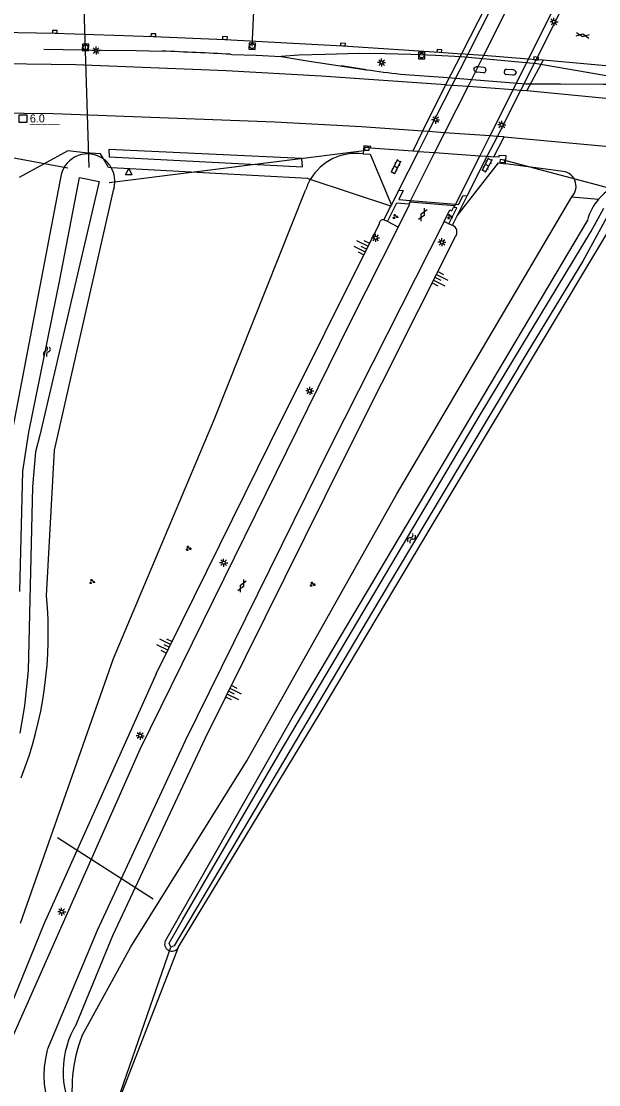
# Model space of a CAD drawing. Extents: x 133000 to 136000, y 400500 to 403500.
# Drawn here: x 134131.9 to 134221.9, y 401012.6 to 401178.4 of the extents above; entities that cross this region are included whole.
import ezdxf

# ---------------------------------------------------------------- set-up
doc = ezdxf.new("R2010")
doc.units = 0
for name, color, linetype in [('gg-afsc-faunaraster', 7, 'Continuous'), ('gg-afsc-hekwerk', 7, 'Continuous'), ('gg-bbg-pilaar viaduct of brug', 7, 'Continuous'), ('gg-knt-BGT kruinlijn', 7, 'Continuous'), ('gg-knt-bovenkant onderkant talud', 7, 'Continuous'), ('gg-knt-verharding', 7, 'Continuous'), ('gg-knt-verharding nz', 7, 'Continuous'), ('gg-kntw-bovenkant insteek waterloop', 7, 'Continuous'), ('gg-kntw-greppel-droge sloot', 7, 'Continuous'), ('gg-kntw-waterlijn', 7, 'Continuous'), ('gg-kwrk-duiker nz buis', 7, 'Continuous'), ('gg-kwrk-kunstwerk', 7, 'Continuous'), ('gg-kwrk-kunstwerk niveau 01', 7, 'Continuous'), ('gt-anno-nummer hm paal', 7, 'Continuous'), ('gt-grn-groengrens', 7, 'Continuous'), ('gt-grn-weggrens', 7, 'Continuous'), ('gt-knt-geleideconstructie', 7, 'Continuous'), ('gt-symb-gesloten verharding', 7, 'Continuous'), ('gt-symb-groenvak', 7, 'Continuous'), ('gt-symb-hm paal', 7, 'Continuous'), ('gt-symb-klinker verharding', 7, 'Continuous'), ('gt-symb-kolk', 7, 'Continuous'), ('gt-symb-lichtmast', 7, 'Continuous'), ('gt-symb-rioolschacht', 7, 'Continuous'), ('gt-symb-talud symbool', 7, 'Continuous'), ('gt-symb-waterafsluiter', 7, 'Continuous'), ('gt-symb-watersymbool', 7, 'Continuous')]:
    doc.layers.add(name, color=color, linetype=linetype)

# ---------------------------------------------------------------- blocks, each defined once
blk = doc.blocks.new('gt0-KOLK')
at = {"layer": 'gt-symb-kolk'}
blk.add_lwpolyline([(0, 0), (0.38, 0), (0.38, 0.4), (-0.37, 0.4), (-0.37, 0), (0, 0)], dxfattribs=at)
blk = doc.blocks.new('gt0-LMAST')
at = {"layer": 'gt-symb-lichtmast'}
for p, q in [((-0.18, 0.17), (-0.45, 0.44)), ((-0.01, 0.25), (-0.01, 0.62)), ((0.17, 0.17), (0.44, 0.44)), ((-0.26, 0), (-0.63, 0)), ((-0.18, -0.18), (-0.45, -0.45)), ((-0.01, -0.25), (-0.01, -0.63)), ((0.44, -0.45), (0.17, -0.18)), ((0.24, 0), (0.62, 0))]:
    blk.add_line(p, q, dxfattribs=at)
blk.add_circle((-0.01, 0), 0.25, dxfattribs=at)
blk = doc.blocks.new('gt0-GESVH1')
at = {"layer": 'gt-symb-gesloten verharding'}
for p, q in [((-0.99, -0.26), (0.01, 0.24)), ((0.01, -0.26), (-0.99, 0.24)), ((0.01, 0.24), (1.01, -0.26)), ((1.01, 0.24), (0.01, -0.26))]:
    blk.add_line(p, q, dxfattribs=at)
blk = doc.blocks.new('gt0-KL1')
at = {"layer": 'gt-symb-klinker verharding'}
for p, q in [((-1.15, 0.3), (1.15, 0.3)), ((-1, -0.3), (-1, 0.3)), ((-0.5, 0.3), (-0.5, 0.45)), ((0, -0.3), (0, 0.3)), ((0.5, 0.3), (0.5, 0.45)), ((1, -0.3), (1, 0.3)), ((-1.15, -0.3), (1.15, -0.3)), ((-0.5, -0.45), (-0.5, -0.3)), ((0.5, -0.45), (0.5, -0.3))]:
    blk.add_line(p, q, dxfattribs=at)
blk = doc.blocks.new('gt0-RS')
at = {"layer": 'gt-symb-rioolschacht'}
blk.add_lwpolyline([(-0.5, -0.5), (0.5, -0.5), (0.5, 0.5), (-0.5, 0.5)], close=True, dxfattribs=at)
blk.add_circle((0, 0), 0.375, dxfattribs=at)
blk = doc.blocks.new('gt0-WA')
at = {"layer": 'gt-symb-watersymbool'}
for centre, start, end in [((-0.32, 0.02), 28.0725, 151.9275), ((0.43, 0.42), 208.0725, 331.9275), ((-0.32, -0.43), 28.0725, 151.9275), ((0.43, -0.03), 208.0725, 331.9275)]:
    blk.add_arc(centre, 0.425, start, end, dxfattribs=at)
blk = doc.blocks.new('gt0-TALUD_1')
at = {"layer": 'gt-symb-talud symbool'}
for p, q in [((-1, -1), (-1, 0)), ((0.5, -2), (0.5, 0)), ((-0.5, -2), (-0.5, 0)), ((0, -1), (0, 0)), ((1, -1), (1, 0))]:
    blk.add_line(p, q, dxfattribs=at)
blk = doc.blocks.new('gt0-GRVAK')
at = {"layer": 'gt-symb-groenvak'}
for p, q in [((-0.11, 0.19), (-0.23, 0.24)), ((-0.18, 0.15), (0.09, 0.15)), ((-0.09, 0.21), (-0.16, 0.32)), ((-0.05, 0.21), (-0.05, 0.39)), ((0, 0.21), (0.06, 0.32)), ((0.01, 0.19), (0.13, 0.24)), ((0.26, -0.05), (0.2, 0.06)), ((0.3, -0.05), (0.3, 0.13)), ((0.35, -0.05), (0.41, 0.06)), ((-0.25, -0.23), (-0.36, -0.18)), ((-0.32, -0.26), (-0.05, -0.26)), ((-0.23, -0.21), (-0.29, -0.1)), ((-0.18, -0.2), (-0.18, -0.02)), ((-0.14, -0.21), (-0.07, -0.1)), ((-0.12, -0.23), (0, -0.18)), ((0.24, -0.07), (0.12, -0.02)), ((0.17, -0.11), (0.44, -0.11)), ((0.37, -0.07), (0.49, -0.02))]:
    blk.add_line(p, q, dxfattribs=at)
blk = doc.blocks.new('gt0-WAFSL')
at = {"layer": 'gt-symb-waterafsluiter'}
for p, q in [((-0.5, -0.33), (0, 0.67)), ((0, 0.67), (0.5, -0.33)), ((0.5, -0.33), (-0.5, -0.33))]:
    blk.add_line(p, q, dxfattribs=at)
blk = doc.blocks.new('gt0-HMpaal')
at = {"layer": 'gt-symb-hm paal'}
blk.add_lwpolyline([(-0.6, 0.6), (0.6, 0.6), (0.6, -0.6), (-0.6, -0.6)], close=True, dxfattribs=at)

msp = doc.modelspace()

# ---------------------------------------------------------------- linework, layer by layer
at = {"layer": 'gg-afsc-faunaraster'}
msp.add_lwpolyline([(134144.24, 401157.74), (134141.86, 401157.94), (134139.16, 401158.24), (134131.54, 401154.05)], dxfattribs=at)
at = {"layer": 'gg-afsc-hekwerk'}
for p, q in [((134144.71, 401156.96), (134144.24, 401157.74)), ((134189.51, 401149.59), (134176.97, 401153.77))]:
    msp.add_line(p, q, dxfattribs=at)
for points in [[(134145.94, 401155.6), (134145.52, 401155.62), (134144.71, 401156.96)], [(134176.97, 401153.77), (134176.52, 401153.92), (134145.94, 401155.6)]]:
    msp.add_lwpolyline(points, dxfattribs=at)
at = {"layer": 'gg-bbg-pilaar viaduct of brug'}
for p, q in [((134203.09, 401171.33), (134203.06, 401171.33)), ((134204.05, 401171.22), (134203.09, 401171.33)), ((134204.35, 401170.88), (134204.34, 401170.72)), ((134207.24, 401170.75), (134207.21, 401170.49)), ((134207.55, 401170.98), (134208.46, 401170.9)), ((134203.98, 401170.41), (134202.96, 401170.51)), ((134208.55, 401170.05), (134207.48, 401170.15))]:
    msp.add_line(p, q, dxfattribs=at)
for centre, radius, start, end in [((134203, 401170.69), 0.644, 84.3695, 154.1173), ((134203.04, 401171.15), 0.644, 195.6872, 240.3909), ((134203.04, 401171.16), 0.658, 240.5941, 263.1005), ((134204, 401170.75), 0.337, 265.9363, 355.1614), ((134204.01, 401170.88), 0.338, 359.975, 82.1786), ((134207.55, 401170.66), 0.32, 89.8543, 164.6529), ((134208.45, 401170.19), 0.706, 20.0302, 88.7607), ((134207.53, 401170.47), 0.323, 174.8818, 260.4784), ((134208.6, 401170.59), 0.535, 264.2303, 343.4292)]:
    msp.add_arc(centre, radius, start, end, dxfattribs=at)
at = {"layer": 'gg-knt-BGT kruinlijn'}
for p, q in [((134182.39, 401110.61), (134199.61, 401144.85)), ((134160.63, 401066.66), (134182.39, 401110.61)), ((134152.95, 401076.65), (134135.39, 401037.62)), ((134146.19, 401035.83), (134160.63, 401066.66)), ((134135.39, 401037.62), (134126.26, 401015.13)), ((134140.5, 401022.08), (134146.19, 401035.83))]:
    msp.add_line(p, q, dxfattribs=at)
msp.add_lwpolyline([(134152.95, 401076.65), (134170.76, 401112.81), (134187.71, 401146.81)], dxfattribs=at)
for centre, radius, start, end in [((134188.31, 401146.88), 0.607, 77.8115, 186.4309), ((134198.68, 401145.55), 1.16, 323.3097, 67.6114), ((134152.73, 401014.63), 14.32, 148.6447, 209.1066)]:
    msp.add_arc(centre, radius, start, end, dxfattribs=at)
at = {"layer": 'gg-knt-bovenkant onderkant talud'}
for p, q in [((134216.02, 401155.04), (134207.41, 401156.18)), ((134161.92, 401116.17), (134176.23, 401152.1))]:
    msp.add_line(p, q, dxfattribs=at)
msp.add_lwpolyline([(134141.35, 401020.16), (134148.99, 401034.06), (134167.08, 401063.08), (134190.43, 401104.61), (134217.74, 401151.06)], dxfattribs=at)
for centre, radius, start, end in [((134184.04, 401149.64), 8.19, 81.9014, 149.7715), ((134216.08, 401152.71), 2.33, 315.1357, 91.47), ((134184.01, 401149.65), 8.16, 149.7381, 162.5226), ((134162.24, 401011.96), 22.44, 158.5636, 191.0401)]:
    msp.add_arc(centre, radius, start, end, dxfattribs=at)
at = {"layer": 'gg-knt-verharding'}
for p, q in [((134200.52, 401173.35), (134198.06, 401168.55)), ((134213.26, 401172.35), (134210.75, 401167.66)), ((134213.26, 401172.35), (134212.2, 401172.44)), ((134209.81, 401167.72), (134210.75, 401167.66)), ((134194.47, 401161.3), (134192.95, 401158.2)), ((134205.6, 401157.31), (134207.2, 401160.4)), ((134207.2, 401160.4), (134206.14, 401160.47)), ((134193.85, 401158.14), (134192.95, 401158.2)), ((134204.57, 401157.38), (134205.6, 401157.31))]:
    msp.add_line(p, q, dxfattribs=at)
for points in [[(134119.8, 401176.91), (134137.11, 401176.61), (134152.48, 401176.09), (134163.64, 401175.62), (134182.04, 401174.62), (134197.07, 401173.62), (134200.52, 401173.35)], [(134466.25, 401127.76), (134452.28, 401131.5), (134437.23, 401135.37), (134422.21, 401139.05), (134407.27, 401142.51), (134392.18, 401145.84), (134377.26, 401148.96), (134362.12, 401151.96), (134347.16, 401154.74), (134332.12, 401157.39), (134317.08, 401159.86), (134302.02, 401162.15), (134287.1, 401164.29), (134272.17, 401166.21), (134257.18, 401167.98), (134242.13, 401169.67), (134227.09, 401171.15), (134213.26, 401172.35)], [(134163.85, 401170.73), (134140.34, 401171.64), (134121.22, 401171.92), (134113.97, 401171.97), (134106.72, 401171.96), (134098.14, 401171.83), (134089.55, 401171.63), (134081.83, 401171.39), (134074.11, 401171.09), (134066.33, 401170.73), (134058.56, 401170.3), (134051.55, 401169.82), (134044.55, 401169.28), (134030.02, 401168.01), (134014.96, 401166.51), (134007.56, 401165.7), (134000, 401164.71)], [(134198.06, 401168.55), (134178.66, 401169.89), (134163.85, 401170.73)], [(134210.75, 401167.66), (134244.46, 401164.38), (134297.88, 401157.65), (134336.32, 401151.51), (134370.15, 401145.23), (134424.79, 401133.18), (134461.82, 401123.69), (134464.32, 401122.98)], [(134194.47, 401161.3), (134184.94, 401161.97), (134171.45, 401162.72), (134136.9, 401163.99), (134122.94, 401164.18), (134112.7, 401164.2), (134098.86, 401164.12), (134091.89, 401164.01), (134084.93, 401163.83), (134077.86, 401163.57), (134070.79, 401163.23), (134063.51, 401162.82), (134057.07, 401162.39)], [(134192.95, 401158.2), (134186.38, 401158.66), (134186.41, 401158.9), (134185.31, 401159), (134185.2, 401157.75)], [(134207.2, 401160.4), (134239.36, 401157.47), (134296.09, 401150.56), (134334.84, 401144.39), (134364.84, 401138.82), (134422.97, 401126.18), (134459.31, 401116.9), (134461.61, 401116.24)], [(134185.2, 401157.75), (134186.32, 401157.71), (134189.61, 401149.78)], [(134207.41, 401156.18), (134207.5, 401157.44), (134206.39, 401157.49), (134206.38, 401157.25), (134205.6, 401157.31)], [(134199.86, 401148.07), (134206.29, 401156.38), (134207.41, 401156.18)], [(134190.67, 401146.32), (134183.06, 401131.29), (134150.39, 401064.88), (134130.54, 401020.06), (134122.62, 401000)], [(134197.86, 401147.22), (134179.99, 401111.98), (134157.44, 401066.19), (134143.74, 401036.64), (134135.92, 401017.99)], [(134131.76, 401037.79), (134146.27, 401079.03), (134161.92, 401116.17)]]:
    msp.add_lwpolyline(points, dxfattribs=at)
msp.add_arc((134151.4, 401014.03), 15.97, 165.6696, 241.4805, dxfattribs=at)
at = {"layer": 'gg-knt-verharding nz'}
for p, q in [((134201.52, 401173.27), (134200.52, 401173.35)), ((134203.98, 401173.08), (134201.52, 401173.27)), ((134210.96, 401172.54), (134203.98, 401173.08)), ((134198.06, 401168.55), (134199.09, 401168.48)), ((134199.09, 401168.48), (134201.57, 401168.3)), ((134201.57, 401168.3), (134208.58, 401167.81)), ((134208.58, 401167.81), (134209.81, 401167.72)), ((134195.42, 401161.23), (134194.47, 401161.3)), ((134197.92, 401161.05), (134195.42, 401161.23)), ((134204.94, 401160.56), (134197.92, 401161.05)), ((134206.14, 401160.47), (134204.94, 401160.56))]:
    msp.add_line(p, q, dxfattribs=at)
msp.add_lwpolyline([(134212.2, 401172.44), (134212.16, 401172.44), (134210.96, 401172.54)], dxfattribs=at)
at = {"layer": 'gg-kntw-bovenkant insteek waterloop'}
msp.add_line((134146.37, 401152.48), (134146.32, 401152.29), dxfattribs=at)
for points in [[(134138.12, 401154.52), (134129.55, 401109.62), (134129.6, 401091.02)], [(134135.83, 401088.82), (134137.1, 401111.53), (134146.32, 401152.29)], [(134220.18, 401147.4), (134174.48, 401070.45), (134154.39, 401035.07)], [(134156.36, 401033.95), (134178.49, 401070.5), (134195.96, 401099.84), (134225.24, 401148.67)]]:
    msp.add_lwpolyline(points, dxfattribs=at)
for centre, radius, start, end in [((134142.24, 401153.5), 4.25, 54.5302, 166.1393), ((134142.24, 401153.5), 4.25, 29.5601, 54.5302), ((134142.24, 401153.5), 4.25, 346.1396, 29.5483), ((134228.42, 401145.14), 8.55, 79.4578, 139.3902), ((134228.42, 401145.14), 8.55, 139.385, 164.6772), ((134074.05, 401082.94), 62.06, 338.7579, 5.438), ((134155.39, 401034.54), 1.14, 151.838, 328.979)]:
    msp.add_arc(centre, radius, start, end, dxfattribs=at)
at = {"layer": 'gg-kntw-greppel-droge sloot'}
msp.add_lwpolyline([(134145.55, 401158.45), (134145.59, 401157.28), (134175.76, 401155.72), (134175.66, 401157.03), (134145.55, 401158.45)], dxfattribs=at)
at = {"layer": 'gg-kntw-waterlijn'}
for points in [[(134131.69, 401089.52), (134132.14, 401108.26), (134133.06, 401114.34), (134137.92, 401138.11), (134140.99, 401154.07), (134144.06, 401153.44), (134134.78, 401113.9), (134134.12, 401111.29), (134133.65, 401105.83), (134132.96, 401077.17), (134132.42, 401071.66), (134131.65, 401067.39)], [(134223.54, 401148.48), (134219.45, 401141.03), (134210.72, 401126.68), (134187.67, 401088.06), (134156.27, 401035.1), (134155.75, 401034.22), (134155.24, 401034.01), (134154.98, 401034.64), (134157.04, 401038.29), (134172.26, 401064.46), (134203.47, 401117.04), (134220.7, 401145.59), (134222.74, 401149.31)]]:
    msp.add_lwpolyline(points, dxfattribs=at)
at = {"layer": 'gg-kwrk-duiker nz buis'}
for p, q in [((134167.9, 401174.56), (134168.88, 401196.56)), ((134141.24, 401193.98), (134142.44, 401155.61)), ((134145.59, 401153.28), (134185.77, 401158.34)), ((134139.13, 401155.55), (134129.88, 401157.25)), ((134224.91, 401152.05), (134206.96, 401156.83)), ((134137.55, 401051.15), (134152.45, 401041.59)), ((134144.59, 401003.45), (134155.24, 401034.01))]:
    msp.add_line(p, q, dxfattribs=at)
at = {"layer": 'gg-kwrk-kunstwerk'}
for p, q in [((134193.85, 401158.14), (134196.36, 401157.96)), ((134196.36, 401157.96), (134203.38, 401157.47)), ((134203.38, 401157.47), (134204.57, 401157.38)), ((134192.6, 401150.51), (134199.59, 401149.92))]:
    msp.add_line(p, q, dxfattribs=at)
for points in [[(134190.79, 401152.1), (134191.46, 401152.05), (134190.77, 401150.66), (134192.6, 401150.51)], [(134199.59, 401149.92), (134200.1, 401149.87), (134200.79, 401151.26), (134201.44, 401151.2)]]:
    msp.add_lwpolyline(points, dxfattribs=at)
at = {"layer": 'gg-kwrk-kunstwerk niveau 01'}
for p, q in [((134201.52, 401173.27), (134205.36, 401180.84)), ((134207.78, 401180.64), (134203.98, 401173.08)), ((134214.74, 401180.06), (134210.96, 401172.54)), ((134212.2, 401172.44), (134216.01, 401179.95)), ((134199.09, 401168.48), (134201.52, 401173.27)), ((134203.98, 401173.08), (134203.09, 401171.33)), ((134210.96, 401172.54), (134208.58, 401167.81)), ((134209.81, 401167.72), (134212.2, 401172.44)), ((134202.72, 401170.59), (134201.57, 401168.3)), ((134203.09, 401171.33), (134202.72, 401170.59)), ((134195.42, 401161.23), (134199.09, 401168.48)), ((134201.57, 401168.3), (134197.92, 401161.05)), ((134208.58, 401167.81), (134204.94, 401160.56)), ((134206.14, 401160.47), (134209.81, 401167.72)), ((134193.85, 401158.14), (134195.42, 401161.23)), ((134197.92, 401161.05), (134196.36, 401157.96)), ((134204.94, 401160.56), (134203.38, 401157.47)), ((134204.57, 401157.38), (134206.14, 401160.47)), ((134190.79, 401152.1), (134193.85, 401158.14)), ((134196.36, 401157.96), (134192.6, 401150.51)), ((134203.38, 401157.47), (134199.59, 401149.92)), ((134201.44, 401151.2), (134204.57, 401157.38)), ((134189.61, 401149.78), (134190.79, 401152.1)), ((134199.86, 401148.07), (134201.44, 401151.2)), ((134188.44, 401147.48), (134189.51, 401149.59)), ((134189.51, 401149.59), (134189.61, 401149.78)), ((134192.47, 401150.24), (134192.33, 401149.97)), ((134192.6, 401150.51), (134192.47, 401150.24)), ((134199.46, 401149.65), (134192.47, 401150.24)), ((134199.46, 401149.65), (134199.32, 401149.38)), ((134199.59, 401149.92), (134199.46, 401149.65)), ((134188.98, 401147.2), (134188.44, 401147.48)), ((134199.12, 401146.62), (134199.86, 401148.07)), ((134190.67, 401146.32), (134188.98, 401147.2)), ((134198.59, 401146.86), (134197.86, 401147.22)), ((134198.59, 401146.86), (134199.12, 401146.62))]:
    msp.add_line(p, q, dxfattribs=at)
for points in [[(134188.98, 401147.2), (134190.48, 401150.11), (134192.33, 401149.97)], [(134190.67, 401146.32), (134192.48, 401149.9), (134192.33, 401149.97)], [(134197.86, 401147.22), (134198.74, 401149.02), (134199.06, 401148.86), (134199.32, 401149.38)], [(134198.59, 401146.86), (134199.83, 401149.35), (134199.32, 401149.38)]]:
    msp.add_lwpolyline(points, dxfattribs=at)
at = {"layer": 'gt-grn-groengrens'}
for p, q in [((134217.74, 401151.06), (134221.93, 401150.7)), ((134156.36, 401033.95), (134144.83, 401004.35))]:
    msp.add_line(p, q, dxfattribs=at)
at = {"layer": 'gt-grn-weggrens'}
for p, q in [((134204.39, 401180.92), (134200.52, 401173.35)), ((134198.06, 401168.55), (134194.47, 401161.3))]:
    msp.add_line(p, q, dxfattribs=at)
at = {"layer": 'gt-knt-geleideconstructie'}
for points in [[(134135.42, 401174.11), (134144.43, 401173.95), (134149.8, 401173.88), (134153.85, 401173.79)], [(134164.51, 401173.31), (134164.75, 401173.24), (134168.5, 401173.13), (134172.43, 401172.94)], [(134191.02, 401170.19), (134197.68, 401169.72), (134210.59, 401168.66), (134215.99, 401168.68), (134222.65, 401168.62), (134226.59, 401168.64), (134231.89, 401168.54), (134226.69, 401169.33), (134220.12, 401170.44), (134212.28, 401171.82), (134200.5, 401172.91), (134196.49, 401173.1), (134192.66, 401173.25), (134188.65, 401173.38), (134184.59, 401173.39), (134179.3, 401173.28), (134175.2, 401173.13), (134172.43, 401172.94)], [(134172.43, 401172.94), (134176.48, 401172.29), (134185.74, 401170.88), (134181.78, 401171.48)]]:
    msp.add_lwpolyline(points, dxfattribs=at)
for centre, radius, start, end in [((134102.75, 399927.79), 1247.04, 87.16125, 87.65167), ((134217.2, 401391.07), 222.42, 261.8675, 263.239)]:
    msp.add_arc(centre, radius, start, end, dxfattribs=at)

# ---------------------------------------------------------------- block references
at = {"layer": 'gt-symb-gesloten verharding'}
for p, rotation in [((134219.43, 401176.25), -9.84862238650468), ((134194.48, 401148.28), 63.12746100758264), ((134166.31, 401090.38), 63.76806006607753)]:
    msp.add_blockref('gt0-GESVH1', p, dxfattribs=dict(at, rotation=rotation))
at = {"layer": 'gt-symb-groenvak'}
for p in [(134190.21, 401147.97), (134198.73, 401147.95), (134157.96, 401096.21), (134142.92, 401091.05), (134177.29, 401090.62)]:
    msp.add_blockref('gt0-GRVAK', p, dxfattribs=at)
at = {"layer": 'gt-symb-hm paal'}
msp.add_blockref('gt0-HMpaal', (134132.14, 401163.26), dxfattribs=at)
at = {"layer": 'gt-symb-klinker verharding'}
for p, rotation in [((134190.3, 401155.74), -117.20591683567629), ((134204.52, 401156), -117.20591683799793)]:
    msp.add_blockref('gt0-KL1', p, dxfattribs=dict(at, rotation=rotation))
at = {"layer": 'gt-symb-kolk'}
for p, rotation in [((134137.11, 401176.61), -1.949254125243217), ((134152.48, 401176.09), -2.4074138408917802), ((134163.64, 401175.62), -3.154392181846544), ((134182.04, 401174.62), -3.7835902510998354), ((134197.07, 401173.62), -4.4162834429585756), ((134212.16, 401172.44), -4.934985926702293), ((134185.77, 401158.34), -1.7183580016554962), ((134206.96, 401156.83), 175.24111432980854)]:
    msp.add_blockref('gt0-KOLK', p, dxfattribs=dict(at, rotation=rotation))
at = {"layer": 'gt-symb-lichtmast'}
for p in [(134214.98, 401178.36), (134143.56, 401173.88), (134188.08, 401172.01), (134196.5, 401163.09), (134206.84, 401162.28), (134187.15, 401144.67), (134197.49, 401143.97), (134176.89, 401120.8), (134163.46, 401093.99), (134150.44, 401067.01), (134138.2, 401039.56)]:
    msp.add_blockref('gt0-LMAST', p, dxfattribs=at)
at = {"layer": 'gt-symb-rioolschacht'}
for p, rotation in [((134141.91, 401174.37), 177.82163117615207), ((134167.9, 401174.56), 175.1221191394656)]:
    msp.add_blockref('gt0-RS', p, dxfattribs=dict(at, rotation=rotation))
msp.add_blockref('gt0-RS', (134194.33, 401173.1), dxfattribs=at)
at = {"layer": 'gt-symb-talud symbool'}
for p, xscale, yscale, rotation in [((134185.76, 401142.92), 0.9999704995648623, 0.9999704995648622, -116.48817853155), ((134196.46, 401138.47), 0.999524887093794, 0.999524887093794, 63.30677056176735), ((134155, 401080.8), 0.9999864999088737, 0.9999864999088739, -116.23193993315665), ((134164.23, 401073.93), 1.0000479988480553, 1.000047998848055, 64.15238977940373)]:
    msp.add_blockref('gt0-TALUD_1', p, dxfattribs=dict(at, xscale=xscale, yscale=yscale, rotation=rotation))
at = {"layer": 'gt-symb-waterafsluiter'}
msp.add_blockref('gt0-WAFSL', (134148.65, 401154.81), dxfattribs=at)
at = {"layer": 'gt-symb-watersymbool'}
for p, rotation in [((134135.88, 401126.87), 77.1170205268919), ((134192.71, 401097.73), 58.99693247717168)]:
    msp.add_blockref('gt0-WA', p, dxfattribs=dict(at, rotation=rotation))

# ---------------------------------------------------------------- texts
at = {"layer": 'gt-anno-nummer hm paal'}
msp.add_text('6.0', height=1.25, dxfattribs=at).set_placement((134133.23, 401162.66))
at = {"layer": 'gt-symb-hm paal'}
msp.add_text('_____', height=1.25, dxfattribs=at).set_placement((134133.23, 401162.66))

doc.saveas('drawing.dxf')
